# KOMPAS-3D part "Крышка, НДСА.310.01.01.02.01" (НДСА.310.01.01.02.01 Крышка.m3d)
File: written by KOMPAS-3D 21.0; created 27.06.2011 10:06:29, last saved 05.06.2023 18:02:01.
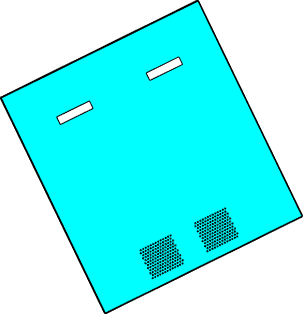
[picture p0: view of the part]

Document properties: Полное имя файла: C:\PLM\НДСА.310.01.01.02.01 Крышка.m3d; Автор: Гривенко; Организация: esto

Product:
- Part/product: Крышка  | designation НДСА.310.01.01.02.01
    Масса: 5.766009
    Форматы листов документа: A2
    additional columns: <item xmlns="http://appius.ru/pdm" xmlns:xs="http://www.w3.org/2001/XMLSchema" x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; <item xmlns="http://appius.ru/pdm" xmlns:xs="http://www.w3.org/2001/XMLSchema" x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; <item xmlns="http://appius.ru/pdm" xmlns:xs="http://www.w3.org/2001/XMLSchema" x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; <item xmlns="http://appius.ru/pdm" xmlns:xs="http://www.w3.org/2001/XMLSchema" x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; <item xmlns="http://appius.ru/pdm" xmlns:xs="http://www.w3.org/2001/XMLSchema" x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; <item xmlns="http://appius.ru/pdm" xmlns:xs="http://www.w3.org/2001/XMLSchema" x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; <item xmlns="http://appius.ru/pdm" xmlns:xs="http://www.w3.org/2001/XMLSchema" x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; <item xmlns="http://appius.ru/pdm" xmlns:xs="http://www.w3.org/2001/XMLSchema" x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

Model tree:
1. Эскиз:1
2. Листовое тело:1
     Расстояние 1 = 10; Радиус сгиба = 5; Коэффициент = 0.424
3. Сгиб:1  (with: Листовое тело:1)
4. Сгиб(1) - Сгиб:1  (labels: Угол 1 замыкания в начале; Отступ 1 замыкания в начале; Угол 2 замыкания в конце; Отступ 2 замыкания в конце)
     Радиус сгиба = 1; Коэффициент = 0.424; Величина сгиба = 10; Радиус сгиба = 1; Коэффициент = 0.424; Величина сгиба = 10; Толщина листового тела = 1; Ширина освобождения сгиба = 2; Глубина освобождения сгиба = 1; Ширина сгиба = 868; Длина продолжения сгиба = 20; Длина 2 = 10
5. Сгиб:2  (with: Листовое тело:1)
6. Сгиб(1) - Сгиб:2  (labels: Угол 1 замыкания в начале; Отступ 1 замыкания в начале; Угол 2 замыкания в конце; Отступ 2 замыкания в конце)
     Радиус сгиба = 1; Коэффициент = 0.424; Величина сгиба = 10; Радиус сгиба = 1; Коэффициент = 0.424; Величина сгиба = 10; Толщина листового тела = 1; Ширина освобождения сгиба = 3; Ширина сгиба = 868; Длина продолжения сгиба = 20; Длина 2 = 10
7. Сгиб:3  (with: Листовое тело:1)
8. Сгиб(1) - Сгиб:3  (labels: Угол 1 замыкания в начале; Отступ 1 замыкания в начале; Угол 2 замыкания в конце; Отступ 2 замыкания в конце)
     Радиус сгиба = 1; Коэффициент = 0.424; Величина сгиба = 10; Радиус сгиба = 1; Коэффициент = 0.424; Величина сгиба = 10; Толщина листового тела = 1; Ширина освобождения сгиба = 2; Глубина освобождения сгиба = 2; Ширина сгиба = 792; Длина продолжения сгиба = 20; Длина 2 = 10
9. Сгиб:4  (with: Листовое тело:1)
10. Сгиб(1) - Сгиб:4  (labels: Угол 1 замыкания в начале; Отступ 1 замыкания в начале; Угол 2 замыкания в конце; Отступ 2 замыкания в конце)
     Радиус сгиба = 1; Коэффициент = 0.424; Величина сгиба = 10; Радиус сгиба = 1; Коэффициент = 0.424; Толщина листового тела = 1; Ширина освобождения сгиба = 1; Глубина освобождения сгиба = 1; Ширина сгиба = 792; Длина продолжения сгиба = 20; Длина 2 = 10
11. Эскиз:3  (with: Листовое тело:1, Сгиб:3, Сгиб:4)
12. Элемент выдавливания:1
     Расстояние 2 = 20
13. Эскиз:4  (with: Сгиб:3)
14. Элемент выдавливания:2
     Расстояние 2 = 10
15. Эскиз:5
16. Элемент выдавливания:3
     Расстояние 1 = 10
17. Массив по сетке:1  (with: Элемент выдавливания:3, Эскиз:5, Сгиб:3, Сгиб:1)  (156 pattern instances)
     Шаг 1 = 10; Угол раствора = 90
18. Развертка  (with: Листовое тело:1)

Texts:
  НДСА.310.01.01.02.01
  Замыкание смежных углов
  Замыкание в начале
  Замыкание в конце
